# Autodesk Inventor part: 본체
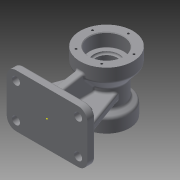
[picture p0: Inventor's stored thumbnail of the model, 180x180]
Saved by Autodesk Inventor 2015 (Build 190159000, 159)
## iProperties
Created: 2015-08
Part Number: 본체
Material: 일반
Document SubType Name: Modeling
Designer: PHO-02
Density: 1 g/cm^3
Appearance: 기본값
Author: PHO-02
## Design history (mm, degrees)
sketch "스케치1"
  geometry: 1 further point
sketch "스케치2"
  geometry: L1 (47, 40)-(-47, 40); L2 (-61, 26)-(-61, -26); L3 (-47, -40)-(47, -40); L4 (61, -26)-(61, 26); L5 (61, 40)-(-61, -40); L6 (-61, 40)-(61, -40); A1 r 14 centre (47, -26) between (47, -40) and (61, -26); A2 r 14 centre (47, 26) between (61, 26) and (47, 40); A3 r 14 centre (-47, 26) between (-47, 40) and (-61, 26); A4 r 14 centre (-47, -26) between (-61, -26) and (-47, -40); 1 further point
  constraints: 12 end point, 8 point on circle, 8 point on line, 8 tangent, 4 centre point, 3 equal radius, 2 midpoint, 2 parallel, 1 horizontal, 1 perpendicular
  dimensions: "d0" = 122 distance of L6.end L5.end; "d1" = 80 distance of L5.end L6.start; "d2" = 14 radius of A1
extrude "돌출1" new body sketch "스케치2" distance "d3" = 12; taper "d4" = 0 deg
sketch "스케치3"
  geometry: L1 (125, -40)-(125, -20); L2 (125, -20)-(116, -14.804); L3 (130, 50)-(130, 30); L4 (130, 30)-(116, 13.315); L5 (116, -14.804)-(116, 13.315); L6 (116, 50)-(116, 30); L7 (110, -40)-(110, -23); L8 (110, -23)-(106, -23); L9 (106, -23)-(106, 27); L10 (116, 30)-(109, 30); L11 (109, 30)-(109, 30); L12 (106, 27)-(106, 27); L13 (90, -40)-(90, 88.543); L14 (116, 50)-(130, 50); L15 (110, -40)-(125, -40); A1 r 3 centre (106, 30) between (106, 27) and (109, 30); 1 further point
  constraints: 30 end point, 3 horizontal, 3 perpendicular, 2 point on circle, 2 tangent, 1 centre point, 1 vertical
  dimensions: "d7" = 35 distance of L13.start L1.start; "d17" = 20 distance of L6.start L6.end; "d22" = 17 distance of L7.start L7.end; "d24" = 7 distance of L6.end L10.end; "d26" = 3 radius of A1
revolve "회전1" sketch "스케치3" stored, may be unused: angle "d27" = 90 deg
sketch "스케치4"
  geometry: L1 (0, 0)-(20.554, 0); 4 further points
  constraints: 2 end point, 2 symmetric about line, 1 horizontal
hole "구멍1" sketch "스케치4" at (-47, 26), (-47, -26), (47, -26), (47, 26) diameter "d31" = 12; stored, may be unused: countersink angle "d35" = 90 deg, drill point angle "d37" = 118 deg; dims "d32" = 6, "d33" = 4, "d34" = 2, "d36" = 8
sketch "스케치5"
  geometry: L1 (12, -40)-(12, -30); L2 (12, -30)-(60.157, -30); L3 (60.157, -30)-(62.211, -22.558); L4 (62.211, -22.558)-(70.657, -16.395); L5 (70.657, -16.395)-(68.374, 22.638); L6 (68.374, 22.638)-(56.733, 33); L7 (12, 30)-(56.733, 37.888); L8 (12, 30)-(57.423, 30); L9 (56.733, 37.888)-(56.733, 33); L10 (12, -30)-(12, 30); L11 (12, 26)-(12, -26) reference; 2 further points
  constraints: 20 end point, 2 horizontal, 1 collinear, 1 equal length, 1 vertical
  dimensions: "d40" = 10 deg angle of L8 L7
extrude "돌출2" join sketch "스케치5" stored distance "d41" = 12; taper "d42" = 0 deg
sketch "스케치6"
  geometry: L1 (61, 12)-(51, 12); L2 (-51, 12)-(-25.091, 83.185); L3 (-6, 64.702)-(-6, 12); L4 (-6, 12)-(-51, 12); L5 (51, 12)-(25.091, 83.185); L6 (51, 12)-(126.753, 12); L7 (51, 12)-(6, 12); L8 (6, 64.702)-(6, 12); A1 r 26 centre (0, 90) between (6, 64.702) and (25.091, 83.185); A2 r 26 centre (0, 90) between (-25.091, 83.185) and (-6, 64.702); 3 further points
  constraints: 16 end point, 4 point on circle, 2 centre point, 2 horizontal, 1 coincident, 1 equal length, 1 vertical
  dimensions: "d44" = 10 distance of point (-61, 12) L2.start; "d46" = 110 deg angle of L6 L5
extrude "돌출3" join sketch "스케치6" stored distance "d47" = 12; taper "d48" = 0 deg
sketch "스케치7"
  geometry: L1 (-18, 30)-(-18, 36); L2 (-30, 30)-(-30, 36); L3 (18, 30)-(18, 36); L4 (30, 30)-(30, 36); A1 r 6 centre (-24, 30) between (-30, 30) and (-18, 30); A2 r 6 centre (-24, 36) between (-18, 36) and (-30, 36); A3 r 6 centre (24, 30) between (18, 30) and (30, 30); A4 r 6 centre (24, 36) between (30, 36) and (18, 36); 1 further point
  constraints: 10 point on circle, 8 end point, 4 centre point, 2 tangent
extrude "돌출4" cut sketch "스케치7" distance "d54" = 12; taper "d55" = 0 deg
sketch "스케치8"
  geometry: L1 (-40, 0)-(-40, 12) reference; 3 further points
  constraints: 1 other
feature "엠보싱1" sketch "스케치8" dims "d0" = 122, "d1" = 80, "d2" = 14, "d60" = 0.5, "d61" = 0
sketch "스케치9"
  geometry: C1 r 40 at (0, 0) reference; 6 further points
  constraints: 6 other
  dimensions: "d66" = 360 deg dimension on C1.centre point (0, 33) (derived)
hole "구멍2" sketch "스케치9" at (0, 33), (-31.385, 10.198), (-19.397, -26.698), (19.397, -26.698), (31.385, 10.198) diameter "d68" = 3.242; stored, may be unused: countersink angle "d72" = 90 deg, drill point angle "d74" = 118 deg; dims "d69" = 10, "d70" = 4, "d71" = 2, "d73" = 13
sketch "스케치10"
  geometry: C1 r 35 at (0, 0) reference; 6 further points
  constraints: 6 other
  dimensions: "d78" = 360 deg dimension on C1.centre point (0, 27) (derived)
hole "구멍3" sketch "스케치10" at (-25.679, 8.343), (0, 27), (25.679, 8.343), (15.87, -21.843), (-15.87, -21.843) diameter "d80" = 3.242; stored, may be unused: countersink angle "d84" = 90 deg, drill point angle "d86" = 118 deg; dims "d81" = 10, "d82" = 4, "d83" = 2, "d85" = 13
fillet "모깎기1" dims "d87" = 3
fillet "모깎기2" dims "d88" = 3, "d89" = 5, "d90" = 0.3
chamfer "모따기1" distance "d91" = 1; stored, may be unused: second distance "d92" = 2, angle "d93" = 45 deg
node "솔리드1"
